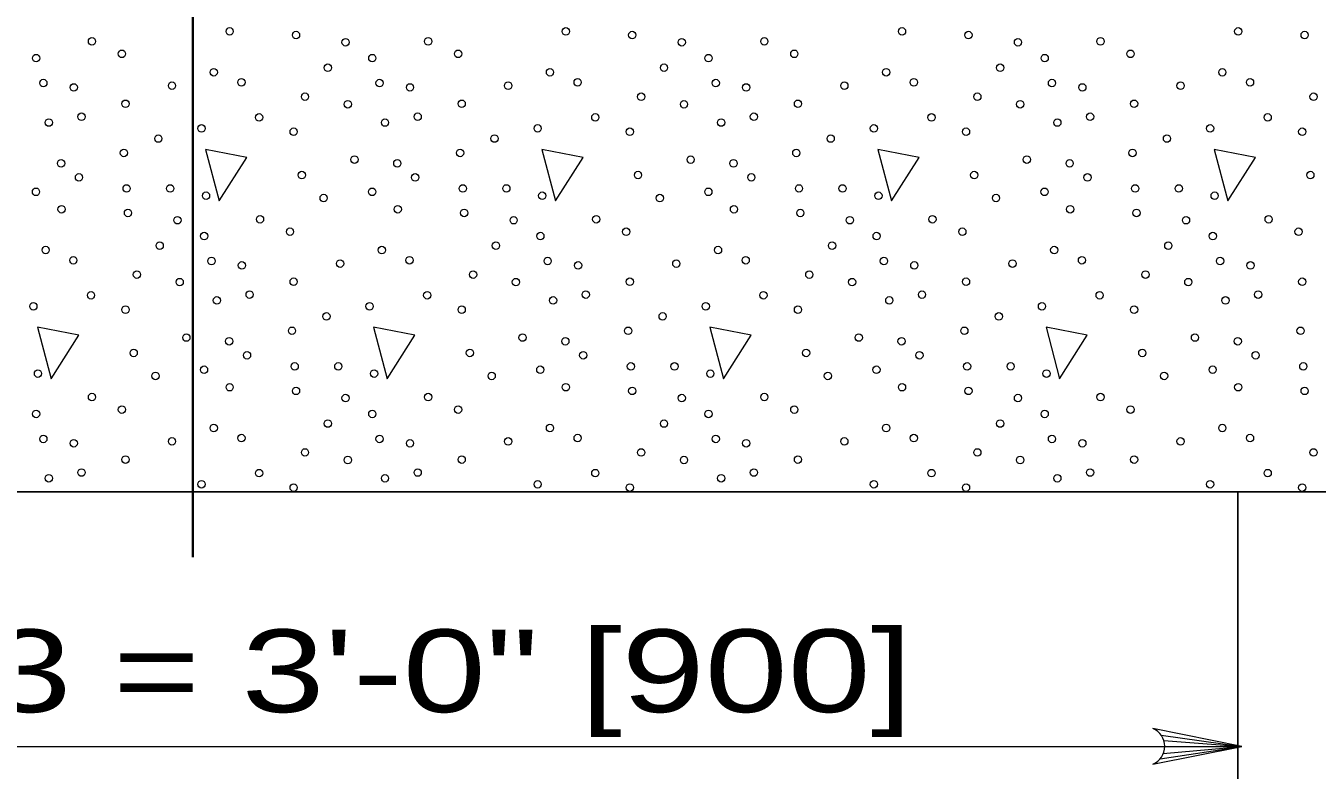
# Model space of a CAD drawing. Extents: x 1083.1 to 1117.1, y 697.4 to 719.4.
# Drawn here: x 1103.719 to 1106.156, y 704.837 to 706.242 of the extents above; entities that cross this region are included whole.
import ezdxf

# ---------------------------------------------------------------- set-up
doc = ezdxf.new("R2010")
doc.units = 0
doc.header["$LTSCALE"] = 0.062
doc.layers.add('1', color=7, linetype='Continuous', lineweight=13)

msp = doc.modelspace()

# ---------------------------------------------------------------- linework, layer by layer
at = {"layer": '1', "lineweight": 35}
msp.add_line((1104.03408, 705.23858), (1104.03408, 707.84983), dxfattribs=at)
at = {"layer": '1', "lineweight": 25}
msp.add_line((1106.00575, 701.25917), (1106.00575, 705.36217), dxfattribs=at)
at = {"layer": '1'}
for p, q in [((1105.86108, 704.903), (1106.01342, 704.88167)), ((1105.86625, 704.89242), (1106.01342, 704.88167)), ((1102.08417, 704.88167), (1105.29683, 704.88167)), ((1105.29683, 704.88167), (1106.01342, 704.88167)), ((1105.85933, 704.85808), (1106.01342, 704.88167)), ((1105.86517, 704.868), (1106.01342, 704.88167)), ((1105.86783, 704.88167), (1106.01342, 704.88167))]:
    msp.add_line(p, q, dxfattribs=at)
for points in [[(1104.05792, 706.00867), (1104.08358, 705.91142), (1104.13575, 705.99358)], [(1104.69233, 706.00867), (1104.718, 705.91142), (1104.77025, 705.99358)], [(1105.32667, 706.00867), (1105.35233, 705.91142), (1105.40458, 705.99358)], [(1105.96117, 706.00867), (1105.98683, 705.91142), (1106.039, 705.99358)], [(1103.74075, 705.67292), (1103.76633, 705.5755), (1103.81858, 705.65767)], [(1104.37508, 705.67292), (1104.40075, 705.5755), (1104.453, 705.65767)], [(1105.00958, 705.67292), (1105.03517, 705.5755), (1105.08742, 705.65767)], [(1105.64392, 705.67292), (1105.66958, 705.5755), (1105.72183, 705.65767)]]:
    msp.add_lwpolyline(points, close=True, dxfattribs=at)
at = {"layer": '1', "lineweight": 25}
msp.add_lwpolyline([(1101.2135, 705.44708), (1101.31708, 705.36217), (1106.77217, 705.36217)], dxfattribs=at)
at = {"layer": '1'}
msp.add_lwpolyline([(1105.84517, 704.848), (1106.01342, 704.88167), (1105.84517, 704.91533)], dxfattribs=at)
msp.add_arc((1105.83161, 704.88169), 0.03631, 292.08605, 67.91218, dxfattribs=at)
for centre in [(1104.10339, 706.23139), (1104.22868, 706.22445), (1104.73779, 706.23139), (1104.86308, 706.22445), (1105.37219, 706.23139), (1105.49748, 706.22445), (1106.00659, 706.23139), (1106.13189, 706.22445), (1103.84355, 706.21264), (1104.3221, 706.21085), (1104.47795, 706.21264), (1104.9565, 706.21085), (1105.11235, 706.21264), (1105.5909, 706.21085), (1105.74675, 706.21264), (1103.73818, 706.1809), (1103.90006, 706.18907), (1104.37258, 706.1809), (1104.53446, 706.18907), (1105.00699, 706.1809), (1105.16886, 706.18907), (1105.64139, 706.1809), (1105.80327, 706.18907), (1104.07341, 706.15432), (1104.28863, 706.16277), (1104.70781, 706.15432), (1104.92303, 706.16277), (1105.34222, 706.15432), (1105.55744, 706.16277), (1105.97662, 706.15432), (1103.75193, 706.13377), (1103.80929, 706.12555), (1103.99459, 706.12896), (1104.12564, 706.13529), (1104.38633, 706.13377), (1104.44369, 706.12555), (1104.62899, 706.12896), (1104.76005, 706.13529), (1105.02073, 706.13377), (1105.07809, 706.12555), (1105.26339, 706.12896), (1105.39445, 706.13529), (1105.65513, 706.13377), (1105.71249, 706.12555), (1105.89779, 706.12896), (1106.02885, 706.13529), (1104.24555, 706.10808), (1104.87995, 706.10808), (1105.51435, 706.10808), (1106.14875, 706.10808), (1103.90693, 706.09471), (1104.32633, 706.09387), (1104.54134, 706.09471), (1104.96073, 706.09387), (1105.17574, 706.09471), (1105.59513, 706.09387), (1105.81014, 706.09471), (1103.76213, 706.05939), (1103.82383, 706.0703), (1104.159, 706.06907), (1104.39653, 706.05939), (1104.45823, 706.0703), (1104.7934, 706.06907), (1105.03094, 706.05939), (1105.09263, 706.0703), (1105.42781, 706.06907), (1105.66534, 706.05939), (1105.72703, 706.0703), (1106.06221, 706.06907), (1103.96884, 706.02917), (1104.05026, 706.0482), (1104.22413, 706.04187), (1104.60324, 706.02917), (1104.68466, 706.0482), (1104.85854, 706.04187), (1105.23764, 706.02917), (1105.31906, 706.0482), (1105.49294, 706.04187), (1105.87205, 706.02917), (1105.95346, 706.0482), (1106.12734, 706.04187), (1103.90381, 706.00196), (1104.53822, 706.00196), (1105.17262, 706.00196), (1105.80702, 706.00196), (1103.78534, 705.98232), (1104.33891, 705.98931), (1104.41974, 705.98232), (1104.97331, 705.98931), (1105.05414, 705.98232), (1105.60771, 705.98931), (1105.68855, 705.98232), (1103.81902, 705.95573), (1104.23957, 705.96027), (1104.45342, 705.95573), (1104.87397, 705.96027), (1105.08782, 705.95573), (1105.50838, 705.96027), (1105.72222, 705.95573), (1106.14278, 705.96027), (1103.73792, 705.92853), (1103.90894, 705.93485), (1103.9912, 705.93485), (1104.37232, 705.92853), (1104.54334, 705.93485), (1104.62561, 705.93485), (1105.00672, 705.92853), (1105.17775, 705.93485), (1105.26001, 705.93485), (1105.64112, 705.92853), (1105.81215, 705.93485), (1105.89441, 705.93485), (1104.05882, 705.92125), (1104.2807, 705.91672), (1104.69322, 705.92125), (1104.9151, 705.91672), (1105.32762, 705.92125), (1105.54951, 705.91672), (1105.96203, 705.92125), (1103.78619, 705.89556), (1103.91148, 705.88862), (1104.42059, 705.89556), (1104.54588, 705.88862), (1105.05499, 705.89556), (1105.18028, 705.88862), (1105.68939, 705.89556), (1105.81469, 705.88862), (1104.0049, 705.87502), (1104.16075, 705.87681), (1104.6393, 705.87502), (1104.79515, 705.87681), (1105.2737, 705.87502), (1105.42955, 705.87681), (1105.9081, 705.87502), (1106.06395, 705.87681), (1104.05538, 705.84508), (1104.21726, 705.85325), (1104.68979, 705.84508), (1104.85166, 705.85325), (1105.32419, 705.84508), (1105.48607, 705.85325), (1105.95859, 705.84508), (1106.12047, 705.85325), (1103.75621, 705.81849), (1103.97143, 705.82694), (1104.39061, 705.81849), (1104.60583, 705.82694), (1105.02501, 705.81849), (1105.24023, 705.82694), (1105.65942, 705.81849), (1105.87464, 705.82694), (1103.80844, 705.79946), (1104.06913, 705.79795), (1104.12649, 705.78972), (1104.31179, 705.79314), (1104.44284, 705.79946), (1104.70353, 705.79795), (1104.76089, 705.78972), (1104.94619, 705.79314), (1105.07725, 705.79946), (1105.33793, 705.79795), (1105.39529, 705.78972), (1105.58059, 705.79314), (1105.71165, 705.79946), (1105.97233, 705.79795), (1106.0297, 705.78972), (1103.92834, 705.77226), (1104.00912, 705.75804), (1104.22413, 705.75888), (1104.56275, 705.77226), (1104.64353, 705.75804), (1104.85854, 705.75888), (1105.19715, 705.77226), (1105.27793, 705.75804), (1105.49294, 705.75888), (1105.83155, 705.77226), (1105.91233, 705.75804), (1106.12734, 705.75888), (1103.8418, 705.73325), (1104.14103, 705.73448), (1104.4762, 705.73325), (1104.77543, 705.73448), (1105.11061, 705.73325), (1105.40983, 705.73448), (1105.74501, 705.73325), (1106.04423, 705.73448), (1103.73305, 705.71237), (1104.07933, 705.72356), (1104.36746, 705.71237), (1104.71373, 705.72356), (1105.00186, 705.71237), (1105.34814, 705.72356), (1105.63626, 705.71237), (1105.98254, 705.72356), (1103.90693, 705.70605), (1104.28604, 705.69334), (1104.54134, 705.70605), (1104.92044, 705.69334), (1105.17574, 705.70605), (1105.55485, 705.69334), (1105.81014, 705.70605), (1104.22102, 705.66614), (1104.85542, 705.66614), (1105.48982, 705.66614), (1106.12422, 705.66614), (1104.02171, 705.65349), (1104.10254, 705.64649), (1104.65611, 705.65349), (1104.73694, 705.64649), (1105.29051, 705.65349), (1105.37134, 705.64649), (1105.92491, 705.65349), (1106.00575, 705.64649), (1103.92237, 705.62444), (1104.13622, 705.61991), (1104.55677, 705.62444), (1104.77062, 705.61991), (1105.19117, 705.62444), (1105.40502, 705.61991), (1105.82558, 705.62444), (1106.03942, 705.61991), (1104.05512, 705.59271), (1104.22614, 705.59903), (1104.3084, 705.59903), (1104.68952, 705.59271), (1104.86055, 705.59903), (1104.94281, 705.59903), (1105.32392, 705.59271), (1105.49495, 705.59903), (1105.57721, 705.59903), (1105.95833, 705.59271), (1106.12935, 705.59903), (1103.74162, 705.58543), (1103.9635, 705.5809), (1104.37602, 705.58543), (1104.5979, 705.5809), (1105.01042, 705.58543), (1105.2323, 705.5809), (1105.64482, 705.58543), (1105.86671, 705.5809), (1103.84355, 705.54099), (1104.10339, 705.55974), (1104.22868, 705.5528), (1104.3221, 705.5392), (1104.47795, 705.54099), (1104.73779, 705.55974), (1104.86308, 705.5528), (1104.9565, 705.5392), (1105.11235, 705.54099), (1105.37219, 705.55974), (1105.49748, 705.5528), (1105.5909, 705.5392), (1105.74675, 705.54099), (1106.00659, 705.55974), (1106.13189, 705.5528), (1103.90006, 705.51742), (1104.53446, 705.51742), (1105.16886, 705.51742), (1105.80327, 705.51742), (1103.73818, 705.50925), (1104.28863, 705.49112), (1104.37258, 705.50925), (1104.92303, 705.49112), (1105.00699, 705.50925), (1105.55744, 705.49112), (1105.64139, 705.50925), (1104.07341, 705.48267), (1104.70781, 705.48267), (1105.34222, 705.48267), (1105.97662, 705.48267), (1103.75193, 705.46213), (1103.80929, 705.4539), (1103.99459, 705.45731), (1104.12564, 705.46364), (1104.38633, 705.46213), (1104.44369, 705.4539), (1104.62899, 705.45731), (1104.76005, 705.46364), (1105.02073, 705.46213), (1105.07809, 705.4539), (1105.26339, 705.45731), (1105.39445, 705.46364), (1105.65513, 705.46213), (1105.71249, 705.4539), (1105.89779, 705.45731), (1106.02885, 705.46364), (1103.90693, 705.42306), (1104.24555, 705.43643), (1104.32633, 705.42222), (1104.54134, 705.42306), (1104.87995, 705.43643), (1104.96073, 705.42222), (1105.17574, 705.42306), (1105.51435, 705.43643), (1105.59513, 705.42222), (1105.81014, 705.42306), (1106.14875, 705.43643), (1103.82383, 705.39865), (1104.159, 705.39742), (1104.45823, 705.39865), (1104.7934, 705.39742), (1105.09263, 705.39865), (1105.42781, 705.39742), (1105.72703, 705.39865), (1106.06221, 705.39742), (1103.76213, 705.38774), (1104.05026, 705.37655), (1104.22413, 705.37022), (1104.39653, 705.38774), (1104.68466, 705.37655), (1104.85854, 705.37022), (1105.03094, 705.38774), (1105.31906, 705.37655), (1105.49294, 705.37022), (1105.66534, 705.38774), (1105.95346, 705.37655), (1106.12734, 705.37022)]:
    msp.add_ellipse(centre, major_axis=(0, 0.00718), ratio=0.944544, dxfattribs=at)

# ---------------------------------------------------------------- texts
at = {"layer": '1', "width": 1.35}
msp.add_text('CB No. 2-3 = 3\'-0" [900]', height=0.156, dxfattribs=at).set_placement((1102.412, 704.94625))

doc.saveas('drawing.dxf')
